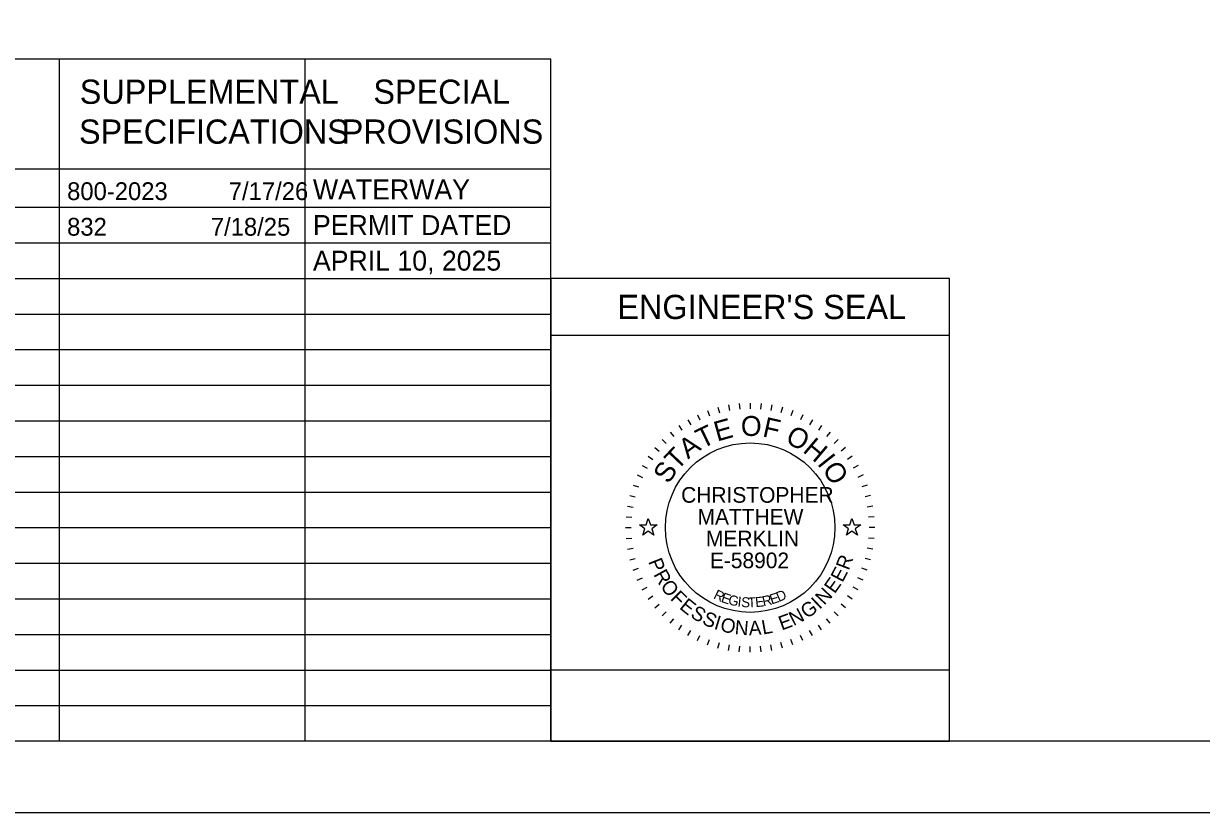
# Model space of a CAD drawing. Extents: x 36.7 to 70.7, y 0 to 22.
# Drawn here: x 56.59 to 64.86, y 0 to 5.54 of the extents above; entities that cross this region are included whole.
import ezdxf

# ---------------------------------------------------------------- set-up
doc = ezdxf.new("R2010")
doc.units = 0
for name, color, linetype in [('Default', 7, 'Continuous'), ('SH_Border', 7, 'Continuous'), ('SH_Cut_Line', 7, 'Continuous'), ('SH_Data', 7, 'Continuous'), ('SH_Seal', 7, 'Continuous'), ('SH_Text', 7, 'Continuous')]:
    doc.layers.add(name, color=color, linetype=linetype)

msp = doc.modelspace()

# ---------------------------------------------------------------- linework, layer by layer
at = {"layer": 'SH_Border'}
msp.add_lwpolyline([(38.1934, 21.4969), (70.1934, 21.4969), (70.1934, 0.4969), (38.1934, 0.4969)], close=True, dxfattribs=at)
at = {"layer": 'SH_Cut_Line'}
msp.add_lwpolyline([(36.6934, -0.0031), (70.6934, -0.0031), (70.6934, 21.9969), (36.6934, 21.9969)], close=True, dxfattribs=at)
at = {"layer": 'SH_Data'}
for p, q in [((46.8434, 5.2887), (60.2934, 5.2887)), ((56.8434, 0.4969), (56.8434, 5.2887)), ((58.5684, 0.4969), (58.5684, 5.2887)), ((60.2934, 0.4969), (60.2934, 5.2887)), ((46.8434, 4.5178), (60.2934, 4.5178)), ((46.8434, 4.2469), (60.2934, 4.2469)), ((46.8434, 3.9969), (60.2934, 3.9969)), ((46.8434, 3.7469), (60.2934, 3.7469)), ((63.0934, 3.7469), (60.2934, 3.7469)), ((60.2934, 3.7469), (60.2934, 0.4969)), ((63.0934, 0.4969), (63.0934, 3.7469)), ((46.8434, 3.4969), (60.2934, 3.4969)), ((63.0934, 3.3469), (60.2934, 3.3469)), ((46.8434, 3.2469), (60.2934, 3.2469)), ((46.8434, 2.9969), (60.2934, 2.9969)), ((46.8434, 2.7469), (60.2934, 2.7469)), ((46.8434, 2.4969), (60.2934, 2.4969)), ((46.8434, 2.2469), (60.2934, 2.2469)), ((46.8434, 1.9969), (60.2934, 1.9969)), ((46.8434, 1.7469), (60.2934, 1.7469)), ((46.8434, 1.4969), (60.2934, 1.4969)), ((46.8434, 1.2469), (60.2934, 1.2469)), ((46.8434, 0.9969), (60.2934, 0.9969)), ((46.8434, 0.7469), (60.2934, 0.7469)), ((63.0934, 0.4969), (60.2934, 0.4969))]:
    msp.add_line(p, q, dxfattribs=at)
msp.add_lwpolyline([(63.0934, 0.4969), (63.0934, 0.9969), (60.2934, 0.9969), (60.2934, 0.4969)], close=True, dxfattribs=at)
at = {"layer": 'SH_Seal'}
for p, q in [((61.3941, 2.8191), (61.4078, 2.7816)), ((61.4669, 2.8421), (61.4773, 2.8035)), ((61.5415, 2.8586), (61.5484, 2.8192)), ((61.6171, 2.8686), (61.6206, 2.8287)), ((61.6934, 2.8719), (61.6934, 2.8319)), ((61.7697, 2.8686), (61.7662, 2.8287)), ((61.8454, 2.8586), (61.8384, 2.8192)), ((61.9199, 2.8421), (61.9095, 2.8035)), ((61.9927, 2.8191), (61.979, 2.7816)), ((61.2559, 2.7547), (61.2759, 2.72)), ((61.3236, 2.7899), (61.3405, 2.7537)), ((62.0632, 2.7899), (62.0463, 2.7537)), ((62.1309, 2.7547), (62.1109, 2.72)), ((61.131, 2.6672), (61.1567, 2.6366)), ((61.1915, 2.7137), (61.2145, 2.6809)), ((62.1953, 2.7137), (62.1723, 2.6809)), ((62.2559, 2.6672), (62.2301, 2.6366)), ((61.0747, 2.6156), (61.103, 2.5873)), ((62.3121, 2.6156), (62.2838, 2.5873)), ((60.9767, 2.4988), (61.0094, 2.4759)), ((61.0231, 2.5594), (61.0538, 2.5336)), ((62.3637, 2.5594), (62.3331, 2.5336)), ((62.4102, 2.4988), (62.3774, 2.4759)), ((60.9356, 2.4344), (60.9703, 2.4144)), ((62.4512, 2.4344), (62.4165, 2.4144)), ((60.9004, 2.3667), (60.9366, 2.3498)), ((62.4864, 2.3667), (62.4502, 2.3498)), ((60.8712, 2.2962), (60.9088, 2.2825)), ((62.5156, 2.2962), (62.4781, 2.2825)), ((60.8482, 2.2234), (60.8869, 2.213)), ((62.5386, 2.2234), (62.5, 2.213)), ((60.8217, 2.0732), (60.8616, 2.0697)), ((60.8317, 2.1489), (60.8711, 2.1419)), ((62.5551, 2.1489), (62.5157, 2.1419)), ((62.5651, 2.0732), (62.5252, 2.0697)), ((60.8184, 1.9969), (60.8584, 1.9969)), ((62.5684, 1.9969), (62.5284, 1.9969)), ((60.8217, 1.9207), (60.8616, 1.9241)), ((62.5651, 1.9207), (62.5252, 1.9241)), ((60.8317, 1.845), (60.8711, 1.8519)), ((62.5551, 1.845), (62.5157, 1.8519)), ((60.8482, 1.7704), (60.8869, 1.7808)), ((62.5386, 1.7704), (62.5, 1.7808)), ((60.8712, 1.6976), (60.9088, 1.7113)), ((62.5156, 1.6976), (62.4781, 1.7113)), ((60.9004, 1.6271), (60.9366, 1.644)), ((60.9356, 1.5594), (60.9703, 1.5794)), ((62.4512, 1.5594), (62.4165, 1.5794)), ((62.4864, 1.6271), (62.4502, 1.644)), ((60.9767, 1.495), (61.0094, 1.518)), ((62.4102, 1.495), (62.3774, 1.518)), ((61.0231, 1.4345), (61.0538, 1.4602)), ((61.0747, 1.3782), (61.103, 1.4065)), ((62.3121, 1.3782), (62.2838, 1.4065)), ((62.3637, 1.4345), (62.3331, 1.4602)), ((61.131, 1.3266), (61.1567, 1.3573)), ((62.2559, 1.3266), (62.2301, 1.3573)), ((61.1915, 1.2802), (61.2145, 1.3129)), ((61.2559, 1.2391), (61.2759, 1.2738)), ((62.1309, 1.2391), (62.1109, 1.2738)), ((62.1953, 1.2802), (62.1723, 1.3129)), ((61.3236, 1.2039), (61.3405, 1.2401)), ((61.3941, 1.1747), (61.4078, 1.2123)), ((61.4669, 1.1517), (61.4773, 1.1904)), ((61.5415, 1.1352), (61.5484, 1.1746)), ((61.6171, 1.1252), (61.6206, 1.1651)), ((61.6934, 1.1219), (61.6934, 1.1619)), ((61.7697, 1.1252), (61.7662, 1.1651)), ((61.8454, 1.1352), (61.8384, 1.1746)), ((61.9199, 1.1517), (61.9095, 1.1904)), ((61.9927, 1.1747), (61.979, 1.2123)), ((62.0632, 1.2039), (62.0463, 1.2401))]:
    msp.add_line(p, q, dxfattribs=at)
for points in [[(60.917, 2.0169), (60.9639, 2.0169), (60.9784, 2.0614), (60.9929, 2.0169), (61.0398, 2.0169), (61.0019, 1.9893), (61.0164, 1.9447), (60.9784, 1.9723), (60.9404, 1.9447), (60.9549, 1.9893)], [(62.347, 2.0169), (62.3939, 2.0169), (62.4084, 2.0614), (62.4229, 2.0169), (62.4698, 2.0169), (62.4319, 1.9893), (62.4464, 1.9447), (62.4084, 1.9723), (62.3704, 1.9447), (62.3849, 1.9893)]]:
    msp.add_lwpolyline(points, close=True, dxfattribs=at)
msp.add_circle((61.6934, 1.9969), 0.595, dxfattribs=at)

# ---------------------------------------------------------------- texts
at = {"layer": 'Default'}
for s, p in [('800-2023', (56.8971, 4.2973)), ('7/17/26', (58.0324, 4.2973)), ('832', (56.8971, 4.0473)), ('7/18/25', (57.9064, 4.0473))]:
    msp.add_text(s, height=0.125, dxfattribs=at).set_placement(p)
at = {"layer": 'SH_Data'}
msp.add_text("ENGINEER'S SEAL", height=0.17, dxfattribs=at).set_placement((60.761, 3.4619))
at = {"layer": 'SH_Seal'}
for s, height, rotation, p in [('E', 0.14, 15.75706, (61.4618, 2.6007)), ('O', 0.14, 359.78119, (61.6281, 2.6412)), ('F', 0.14, 347.43619, (61.7745, 2.6387)), ('T', 0.14, 25.71674, (61.355, 2.5487)), ('O', 0.14, 332.25863, (61.9332, 2.5984)), ('T', 0.14, 46.4344, (61.1817, 2.3934)), ('A', 0.14, 36.47472, (61.2568, 2.475)), ('H', 0.14, 319.91363, (62.0566, 2.533)), ('I', 0.14, 308.36695, (62.1599, 2.4452)), ('S', 0.14, 57.19238, (61.1215, 2.2983)), ('O', 0.14, 303.14906, (62.1956, 2.4058)), ('P', 0.1, 291.49398, (60.9757, 1.759)), ('R', 0.1, 69.23216, (62.3854, 1.6923)), ('R', 0.1, 298.73106, (61.0124, 1.6686)), ('E', 0.1, 61.99508, (62.341, 1.6068)), ('O', 0.1, 306.46664, (61.0589, 1.5852)), ('N', 0.1, 47.02243, (62.2136, 1.4477)), ('E', 0.1, 54.75801, (62.2867, 1.5283)), ('F', 0.1, 314.7068, (61.1277, 1.4952)), ('E', 0.1, 321.43929, (61.1912, 1.4317)), ('R', 0.07, 334.48695, (61.4309, 1.502)), ('E', 0.07, 341.03996, (61.484, 1.477)), ('G', 0.07, 347.47515, (61.5349, 1.4587)), ('I', 0.07, 353.78581, (61.6025, 1.4437)), ('S', 0.07, 356.89262, (61.6292, 1.4398)), ('T', 0.07, 3.00609, (61.6791, 1.4356)), ('E', 0.07, 6.01169, (61.7324, 1.4381)), ('R', 0.07, 11.91844, (61.7859, 1.4443)), ('E', 0.07, 17.68363, (61.8432, 1.4571)), ('D', 0.07, 23.30524, (61.8944, 1.4739)), ('I', 0.1, 43.28703, (62.1803, 1.4183)), ('S', 0.1, 328.67637, (61.2677, 1.3722)), ('N', 0.1, 27.31129, (61.9979, 1.3044)), ('G', 0.1, 35.04687, (62.0915, 1.3539)), ('S', 0.1, 335.91345, (61.3498, 1.3235)), ('I', 0.1, 343.15053, (61.434, 1.2866)), ('O', 0.1, 346.88592, (61.4773, 1.2721)), ('N', 0.1, 355.12608, (61.5822, 1.2487)), ('A', 0.1, 2.86166, (61.6857, 1.2406)), ('L', 0.1, 10.09874, (61.7828, 1.246)), ('E', 0.1, 20.07421, (61.9146, 1.2739))]:
    msp.add_text(s, height=height, rotation=rotation, dxfattribs=at).set_placement(p)
for s, p in [('CHRISTOPHER', (61.2089, 2.1718)), ('MATTHEW', (61.3238, 2.0186)), ('MERKLIN', (61.3833, 1.8653)), ('E-58902', (61.4106, 1.712))]:
    msp.add_text(s, height=0.11, dxfattribs=at).set_placement(p)
at = {"layer": 'SH_Text'}
for s, height, p in [('SUPPLEMENTAL', 0.17, (56.9859, 4.9732)), ('SPECIAL', 0.17, (59.0476, 4.9732)), ('SPECIFICATIONS', 0.17, (56.9805, 4.6932)), ('PROVISIONS', 0.17, (58.8257, 4.6932)), ('WATERWAY', 0.14, (58.6234, 4.3019)), ('PERMIT DATED', 0.14, (58.6234, 4.0519)), ('APRIL 10, 2025', 0.14, (58.6234, 3.8019))]:
    msp.add_text(s, height=height, dxfattribs=at).set_placement(p)

doc.saveas('drawing.dxf')
